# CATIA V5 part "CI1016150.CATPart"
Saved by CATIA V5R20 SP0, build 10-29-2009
Part number: CI1016150
Bounding box of the stored display mesh (mm): x -15 to 15, y -11.829 to 174, z -16.506 to 17.553
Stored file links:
  C:\Users\Raffaele\Desktop\3D X SITO CF\BOLEX\19-INCLINED ASSEMBLY REF_CI\CI1016150.CATPart
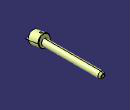
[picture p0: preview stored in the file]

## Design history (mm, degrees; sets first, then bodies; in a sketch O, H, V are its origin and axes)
Set1
  DatumSurface1 to DatumSurface16 "MANIFOLD_SOLID_BREP #385"
  DatumSurface17 to DatumSurface39 "MANIFOLD_SOLID_BREP #1110"
Body1 (main body)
